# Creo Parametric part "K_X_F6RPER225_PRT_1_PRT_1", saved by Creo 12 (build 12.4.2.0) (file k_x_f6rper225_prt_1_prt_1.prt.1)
Units: Custom; MM, KILOGRAM, SECS

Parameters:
  PTC_WM_ITERATION = "0"
  PTC_WM_VERSION = "-.0"
  PTC_WM_LIFECYCLE_STATE = "In Work"
  PTC_WM_LIFECYCLE = "MO_CADDocument"
  PTC_WM_CREATED_BY = "Maximilian Roepper (Z0017RMS: MO)"
  PTC_WM_CREATED_ON = "18-Sep-26 11:36:42 AM"
  PTC_WM_MODIFIED_BY = "Maximilian Roepper (Z0017RMS: MO)"
  PTC_WM_MODIFIED_ON = "18-Sep-26 11:36:46 AM"
  PDMLINKNUMBER = "PDM000071454941"
  PTC_WM_NAME = "k_x_f6rper225_prt_1_prt_1.prt"
  PTC_WM_NUMBER = "PDM000071454941"

Other parameters: WEIGHT, WEIGHT_FACTOR, WEIGHT_ADD, _MASS_TEMP, _DIFF_TEMP, MC_ERRORS, SUPPLIER

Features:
  1. coordinate system
  2. datum plane "PRT_YZ"
  3. datum plane "PRT_XY"
  4. datum plane "PRT_XZ"
  5. coordinate system
  6. datum axis
  7. datum axis
  8. datum axis
  9. coordinate system
  10. imported feature
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
Other named items: PRT, SIEMENS_MO, DRW_VIEW_ORG, PRT_X, PRT_Y, PRT_Z, CS0, ROUGH_GROB

Layers: 00_STD_CSYS-KSYS, 01_STD_PLANES-EBENEN, 02_STD_AXES-ACHSEN, 03_STD_CSYS-KSYS, 24_IMPORT_FEAT-IMPORT_KE

Surfaces: 10 plane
